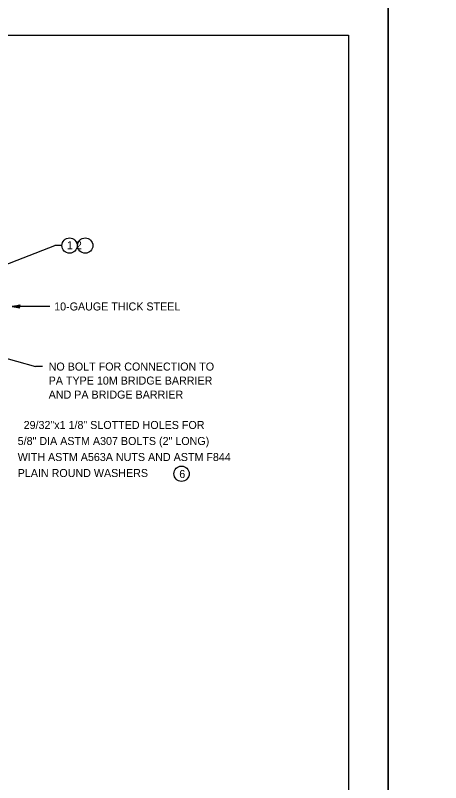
# Model space of a CAD drawing. Extents: x 632007860 to 635435983, y 295418622 to 297794622.
# Drawn here: x 633548035 to 633709860, y 296901105 to 297193122 of the extents above; entities that cross this region are included whole.
import ezdxf

# ---------------------------------------------------------------- set-up
doc = ezdxf.new("R2010")
doc.units = 0
for name, color, linetype in [('1', 7, 'Continuous'), ('PLT-BNDY', 7, 'Continuous'), ('S-DETL-DIMS', 7, 'Continuous'), ('S-DETL-T120', 7, 'Continuous')]:
    doc.layers.add(name, color=color, linetype=linetype)

msp = doc.modelspace()

# ---------------------------------------------------------------- linework, layer by layer
at = {"layer": '1'}
for p, q in [((632888860, 297185622), (633674860, 297185622)), ((633674860, 297185622), (633674860, 296621622))]:
    msp.add_line(p, q, dxfattribs=at)
at = {"layer": 'PLT-BNDY'}
for points in [[(632848860, 297200622), (633689860, 297200622), (633689860, 296606622), (632848860, 296606622)], [(633689860, 297200622), (634530860, 297200622), (634530860, 296606622), (633689860, 296606622)]]:
    msp.add_lwpolyline(points, close=True, dxfattribs=at)
at = {"layer": 'S-DETL-DIMS'}
for p, q in [((633529674, 297092676), (633563103, 297105486)), ((633565750, 297105486), (633563103, 297105486)), ((633561130, 297082335), (633546844, 297082335)), ((633528547, 297067114), (633555733, 297059532)), ((633558379, 297059532), (633555733, 297059532))]:
    msp.add_line(p, q, dxfattribs=at)
msp.add_lwpolyline([(633546844, 297082335), (633549803, 297082890), (633549689, 297082811), (633549575, 297082732), (633549517, 297082632), (633549458, 297082533), (633549441, 297082434), (633549424, 297082335), (633549441, 297082235), (633549458, 297082136), (633549517, 297082037), (633549575, 297081938), (633549689, 297081859), (633549803, 297081780), (633546844, 297082335), (633549689, 297081859), (633549575, 297081938), (633546844, 297082335), (633549517, 297082037), (633549458, 297082136), (633546844, 297082335), (633549441, 297082235), (633549424, 297082335), (633546844, 297082335), (633549441, 297082434), (633549458, 297082533), (633546844, 297082335), (633549517, 297082632), (633549575, 297082732), (633546844, 297082335), (633549689, 297082811)], dxfattribs=at)
for centre in [(633568656, 297105486), (633574626, 297105486), (633611268, 297018678)]:
    msp.add_circle(centre, 2906, dxfattribs=at)

# ---------------------------------------------------------------- texts
at = {"layer": 'S-DETL-T120'}
for s, height, p in [('1 2', 3048, (633567669, 297104119)), ('10-GAUGE THICK STEEL', 3048.01, (633562802, 297080805)), ('NO BOLT FOR CONNECTION TO ', 3048.01, (633560712, 297057933)), ('PA TYPE 10M BRIDGE BARRIER ', 3048.01, (633560712, 297052599)), ('AND PA BRIDGE BARRIER', 3048.01, (633560712, 297047265)), ('  29/32"x1 1/8" SLOTTED HOLES FOR', 3048.07, (633548927, 297035705)), ('5/8" DIA ASTM A307 BOLTS (2" LONG)', 3048.07, (633548927, 297029608)), ('WITH ASTM A563A NUTS AND ASTM F844', 3048.07, (633548927, 297023512)), ('PLAIN ROUND WASHERS', 3048.07, (633548927, 297017416)), ('6', 3048, (633610406, 297017045))]:
    msp.add_text(s, height=height, dxfattribs=at).set_placement(p)

doc.saveas('drawing.dxf')
